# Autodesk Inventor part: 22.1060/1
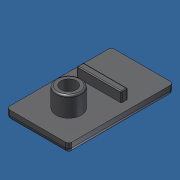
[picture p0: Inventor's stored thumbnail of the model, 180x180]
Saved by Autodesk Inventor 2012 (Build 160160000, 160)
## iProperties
Created: 2007-01
Part Number: 22.1060/1
Document SubType Name: Modeling
Designer: Andy Moles
Material: ABS Plastic
Density: 1.06 g/cm^3
Mass: 2.14066 g
Surface Area: 17.656 cm^2
Volume: 2.01949 cm^3
Description: END CAP 19X32 GRAY
Vendor: S
Author: Andy Moles
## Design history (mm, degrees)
sketch "Sketch1"
  geometry: L1 (-9.5, 22.5)-(9.5, 22.5); L2 (9.5, 22.5)-(9.5, -9.5); L3 (9.5, -9.5)-(-9.5, -9.5); L4 (-9.5, -9.5)-(-9.5, 22.5); 1 further point
  constraints: 8 end point, 2 parallel, 1 horizontal, 1 perpendicular
  dimensions: "WIDTH1" = 32 distance of L1.end L2.end; "WIDTH2" = 19 distance of L1.start L1.end; "d2" = 22.5 distance from line of point (0, 0) L1; "d3" = 9.5 distance from line of point (0, 0) L2
extrude "Extrusion1" new body sketch "Sketch1" distance "d4" = 3; taper "d5" = 0 deg
fillet "Fillet1" dims "d6" = 1
fillet "Fillet2" dims "d7" = 1.5
sketch "Sketch2"
  geometry: L1 (8.5, -9.5)-(-8.5, -9.5) reference; L2 (-9.5, -8.5)-(-9.5, 21.5) reference; C1 r 2.375 at (0, 0); C2 r 3.825 at (0, 0)
  constraints: 2 centre point, 1 coincident
  dimensions: "d8" = 4.75 diameter of C1; "d9" = 7.65 diameter of C2; "d10" = 9.5 distance from line of C1.centre L1; "d11" = 9.5 distance from line of C1.centre L2
extrude "Extrusion2" join sketch "Sketch2" distance "d12" = 6; taper "d13" = 0 deg
fillet "Fillet3" dims "d14" = 0.5
sketch "Sketch3"
  geometry: L1 (-8.5, 22.5)-(8.5, 22.5) reference; L2 (-6.73, 11.24)-(6.73, 11.24); L3 (6.73, 11.24)-(6.73, 9.31); L4 (6.73, 9.31)-(-6.73, 9.31); L5 (-6.73, 9.31)-(-6.73, 11.24); 2 further points
  constraints: 8 end point, 2 midpoint, 2 parallel, 1 horizontal, 1 perpendicular, 1 vertical alignment
  dimensions: "d15" = 13.46 distance of L2.start L2.end; "d16" = 1.93 distance of L2.end L3.end; "d17" = 13.19 distance between parallel lines of L4 L1
extrude "Extrusion3" join sketch "Sketch3" distance "d18" = 3; taper "d19" = 0 deg
fillet "Fillet4" dims "d20" = 0.25
body "Solid1"
